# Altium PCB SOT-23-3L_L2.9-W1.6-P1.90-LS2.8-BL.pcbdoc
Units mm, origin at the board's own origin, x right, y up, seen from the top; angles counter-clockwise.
Board outline 15.81 x 16.54 mm, 2 copper layers (Top Layer, Bottom Layer), stack 0 mm thick; 1 components, 0 nets, 3 pads, 0 vias.
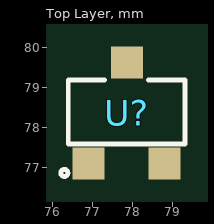
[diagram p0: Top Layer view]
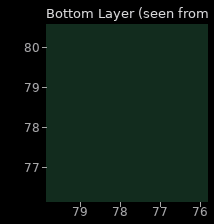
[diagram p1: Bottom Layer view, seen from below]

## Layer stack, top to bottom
Top Layer: signal copper (thickness not stored)
Bottom Layer: signal copper (thickness not stored)

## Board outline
85.664,69.85 69.85,69.85 69.85,86.39 85.664,86.39

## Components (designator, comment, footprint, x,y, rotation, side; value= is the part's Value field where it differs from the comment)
U? "" SOT-23-3L_L2.9-W1.6-P1.90-LS2.8-BL 77.849,78.375 r0 top

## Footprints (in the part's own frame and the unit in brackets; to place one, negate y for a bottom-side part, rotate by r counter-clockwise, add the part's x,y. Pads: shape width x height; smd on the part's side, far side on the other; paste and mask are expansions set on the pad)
SOT-23-3L_L2.9-W1.6-P1.90-LS2.8-BL [mm]
  rect 0.8x0.8 smd paste+0 mask+0.05: 1(-0.95,-1.265) 2(0.95,-1.265) 3(0.005,1.265)
  silkscreen extent -1.65,-1.59 1.46,0.82

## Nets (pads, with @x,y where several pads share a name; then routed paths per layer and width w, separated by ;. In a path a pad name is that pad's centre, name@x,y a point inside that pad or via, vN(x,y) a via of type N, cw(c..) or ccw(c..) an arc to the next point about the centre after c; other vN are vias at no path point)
pads on no net: U?.1 U?.2 U?.3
